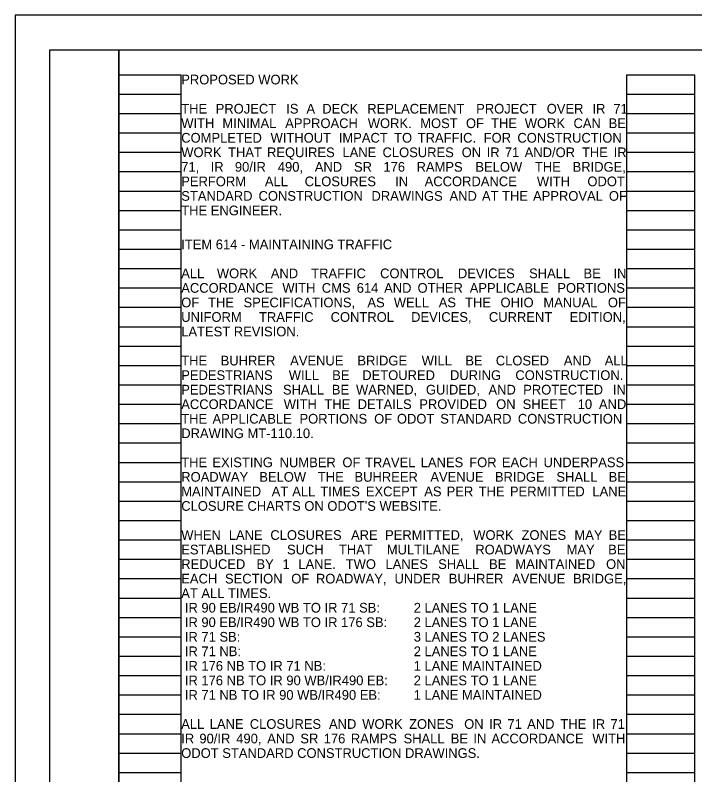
# Model space of a CAD drawing. Extents: x 0 to 43.6, y -18 to 22.
# Drawn here: x 0 to 9.82, y 11.03 to 22 of the extents above; entities that cross this region are included whole.
import ezdxf

# ---------------------------------------------------------------- set-up
doc = ezdxf.new("R2010")
doc.units = 0
for name, color, linetype in [('SH_Border', 7, 'Continuous'), ('SH_Cut_Line', 7, 'Continuous'), ('SH_Data', 7, 'Continuous'), ('SH_Text', 7, 'Continuous')]:
    doc.layers.add(name, color=color, linetype=linetype)

msp = doc.modelspace()

# ---------------------------------------------------------------- linework, layer by layer
at = {"layer": 'SH_Border'}
for points in [[(0.5, 21.5), (1.5, 21.5), (1.5, 0.5), (0.5, 0.5)], [(1.5, 21.5), (33.5, 21.5), (33.5, 0.5), (1.5, 0.5)]]:
    msp.add_lwpolyline(points, close=True, dxfattribs=at)
at = {"layer": 'SH_Cut_Line'}
msp.add_lwpolyline([(0, 0), (34, 0), (34, 22), (0, 22)], close=True, dxfattribs=at)
at = {"layer": 'SH_Data'}
for p, q in [((1.5, 0.98), (1.5, 21.14)), ((1.5, 21.14), (2.4, 21.14)), ((2.4, 0.98), (2.4, 21.14)), ((8.84, 0.98), (8.84, 21.14)), ((8.84, 21.14), (9.82, 21.14)), ((9.82, 0.98), (9.82, 21.14)), ((1.5, 20.86), (2.4, 20.86)), ((8.84, 20.86), (9.82, 20.86)), ((1.5, 20.58), (2.4, 20.58)), ((8.84, 20.58), (9.82, 20.58)), ((1.5, 20.3), (2.4, 20.3)), ((8.84, 20.3), (9.82, 20.3)), ((1.5, 20.02), (2.4, 20.02)), ((8.84, 20.02), (9.82, 20.02)), ((1.5, 19.74), (2.4, 19.74)), ((8.84, 19.74), (9.82, 19.74)), ((1.5, 19.46), (2.4, 19.46)), ((8.84, 19.46), (9.82, 19.46)), ((1.5, 19.18), (2.4, 19.18)), ((8.84, 19.18), (9.82, 19.18)), ((1.5, 18.9), (2.4, 18.9)), ((8.84, 18.9), (9.82, 18.9)), ((1.5, 18.62), (2.4, 18.62)), ((8.84, 18.62), (9.82, 18.62)), ((1.5, 18.34), (2.4, 18.34)), ((8.84, 18.34), (9.82, 18.34)), ((1.5, 18.06), (2.4, 18.06)), ((8.84, 18.06), (9.82, 18.06)), ((1.5, 17.78), (2.4, 17.78)), ((8.84, 17.78), (9.82, 17.78)), ((1.5, 17.5), (2.4, 17.5)), ((8.84, 17.5), (9.82, 17.5)), ((1.5, 17.22), (2.4, 17.22)), ((8.84, 17.22), (9.82, 17.22)), ((1.5, 16.94), (2.4, 16.94)), ((8.84, 16.94), (9.82, 16.94)), ((1.5, 16.66), (2.4, 16.66)), ((8.84, 16.66), (9.82, 16.66)), ((1.5, 16.38), (2.4, 16.38)), ((8.84, 16.38), (9.82, 16.38)), ((1.5, 16.1), (2.4, 16.1)), ((8.84, 16.1), (9.82, 16.1)), ((1.5, 15.82), (2.4, 15.82)), ((8.84, 15.82), (9.82, 15.82)), ((1.5, 15.54), (2.4, 15.54)), ((8.84, 15.54), (9.82, 15.54)), ((1.5, 15.26), (2.4, 15.26)), ((8.84, 15.26), (9.82, 15.26)), ((1.5, 14.98), (2.4, 14.98)), ((8.84, 14.98), (9.82, 14.98)), ((1.5, 14.7), (2.4, 14.7)), ((8.84, 14.7), (9.82, 14.7)), ((1.5, 14.42), (2.4, 14.42)), ((8.84, 14.42), (9.82, 14.42)), ((1.5, 14.14), (2.4, 14.14)), ((8.84, 14.14), (9.82, 14.14)), ((1.5, 13.86), (2.4, 13.86)), ((8.84, 13.86), (9.82, 13.86)), ((1.5, 13.58), (2.4, 13.58)), ((8.84, 13.58), (9.82, 13.58)), ((1.5, 13.3), (2.4, 13.3)), ((8.84, 13.3), (9.82, 13.3)), ((1.5, 13.02), (2.4, 13.02)), ((8.84, 13.02), (9.82, 13.02)), ((1.5, 12.74), (2.4, 12.74)), ((8.84, 12.74), (9.82, 12.74)), ((1.5, 12.46), (2.4, 12.46)), ((8.84, 12.46), (9.82, 12.46)), ((1.5, 12.18), (2.4, 12.18)), ((8.84, 12.18), (9.82, 12.18)), ((1.5, 11.9), (2.4, 11.9)), ((8.84, 11.9), (9.82, 11.9)), ((1.5, 11.62), (2.4, 11.62)), ((8.84, 11.62), (9.82, 11.62)), ((1.5, 11.34), (2.4, 11.34)), ((8.84, 11.34), (9.82, 11.34)), ((1.5, 11.06), (2.4, 11.06)), ((8.84, 11.06), (9.82, 11.06))]:
    msp.add_line(p, q, dxfattribs=at)

# ---------------------------------------------------------------- texts
at = {"layer": 'SH_Text'}
for s, p in [('PROPOSED WORK', (2.4, 21)), ('THE ', (2.4, 20.579)), ('PROJECT ', (2.898, 20.579)), ('IS ', (3.917, 20.579)), ('A ', (4.209, 20.579)), ('DECK ', (4.438, 20.579)), ('REPLACEMENT ', (5.088, 20.579)), ('PROJECT ', (6.662, 20.579)), ('OVER ', (7.682, 20.579)), ('IR ', (8.343, 20.579)), ('71 ', (8.645, 20.579)), ('WITH ', (2.4, 20.369)), ('MINIMAL ', (2.995, 20.369)), ('APPROACH ', (3.902, 20.369)), ('WORK. ', (5.096, 20.369)), ('MOST ', (5.854, 20.369)), ('OF ', (6.515, 20.369)), ('THE ', (6.878, 20.369)), ('WORK ', (7.365, 20.369)), ('CAN ', (8.069, 20.369)), ('BE ', (8.577, 20.369)), ('COMPLETED ', (2.4, 20.159)), ('WITHOUT ', (3.691, 20.159)), ('IMPACT ', (4.677, 20.159)), ('TO ', (5.476, 20.159)), ('TRAFFIC. ', (5.818, 20.159)), ('FOR ', (6.771, 20.159)), ('CONSTRUCTION ', (7.258, 20.159)), ('WORK ', (2.4, 19.949)), ('THAT ', (3.076, 19.949)), ('REQUIRES ', (3.64, 19.949)), ('LANE ', (4.73, 19.949)), ('CLOSURES ', (5.309, 19.949)), ('ON ', (6.453, 19.949)), ('IR ', (6.814, 19.949)), ('71 ', (7.077, 19.949)), ('AND/OR ', (7.363, 19.949)), ('THE ', (8.191, 19.949)), ('IR ', (8.65, 19.949)), ('71, ', (2.4, 19.739)), ('IR ', (2.825, 19.739)), ('90/IR ', (3.175, 19.739)), ('490, ', (3.796, 19.739)), ('AND ', (4.33, 19.739)), ('SR ', (4.896, 19.739)), ('176 ', (5.322, 19.739)), ('RAMPS ', (5.801, 19.739)), ('BELOW ', (6.651, 19.739)), ('THE ', (7.511, 19.739)), ('BRIDGE, ', (8.056, 19.739)), ('PERFORM ', (2.4, 19.529)), ('ALL ', (3.609, 19.529)), ('CLOSURES ', (4.184, 19.529)), ('IN ', (5.491, 19.529)), ('ACCORDANCE ', (5.918, 19.529)), ('WITH ', (7.54, 19.529)), ('ODOT ', (8.27, 19.529)), ('STANDARD ', (2.4, 19.319)), ('CONSTRUCTION ', (3.517, 19.319)), ('DRAWINGS ', (5.149, 19.319)), ('AND ', (6.277, 19.319)), ('AT ', (6.746, 19.319)), ('THE ', (7.037, 19.319)), ('APPROVAL ', (7.484, 19.319)), ('OF ', (8.58, 19.319)), ('THE ENGINEER.', (2.4, 19.109)), ('ITEM 614 - MAINTAINING TRAFFIC', (2.4, 18.619)), ('ALL ', (2.4, 18.2)), ('WORK ', (2.915, 18.2)), ('AND ', (3.694, 18.2)), ('TRAFFIC ', (4.278, 18.2)), ('CONTROL ', (5.274, 18.2)), ('DEVICES ', (6.398, 18.2)), ('SHALL ', (7.427, 18.2)), ('BE ', (8.214, 18.2)), ('IN ', (8.646, 18.2)), ('ACCORDANCE ', (2.4, 17.99)), ('WITH ', (3.861, 17.99)), ('CMS ', (4.431, 17.99)), ('614 ', (4.936, 17.99)), ('AND ', (5.332, 17.99)), ('OTHER ', (5.815, 17.99)), ('APPLICABLE ', (6.569, 17.99)), ('PORTIONS ', (7.835, 17.99)), ('OF ', (2.4, 17.78)), ('THE ', (2.788, 17.78)), ('SPECIFICATIONS, ', (3.3, 17.78)), ('AS ', (5.09, 17.78)), ('WELL ', (5.472, 17.78)), ('AS ', (6.121, 17.78)), ('THE ', (6.502, 17.78)), ('OHIO ', (7.014, 17.78)), ('MANUAL ', (7.634, 17.78)), ('OF ', (8.566, 17.78)), ('UNIFORM ', (2.4, 17.57)), ('TRAFFIC ', (3.523, 17.57)), ('CONTROL ', (4.559, 17.57)), ('DEVICES, ', (5.722, 17.57)), ('CURRENT ', (6.846, 17.57)), ('EDITION, ', (8.012, 17.57)), ('LATEST REVISION.  ', (2.4, 17.36)), ('THE ', (2.4, 16.94)), ('BUHRER ', (2.97, 16.94)), ('AVENUE ', (3.974, 16.94)), ('BRIDGE ', (4.946, 16.94)), ('WILL ', (5.875, 16.94)), ('BE ', (6.506, 16.94)), ('CLOSED ', (6.946, 16.94)), ('AND ', (7.929, 16.94)), ('ALL ', (8.52, 16.94)), ('PEDESTRIANS ', (2.4, 16.73)), ('WILL ', (3.954, 16.73)), ('BE ', (4.581, 16.73)), ('DETOURED ', (5.016, 16.73)), ('DURING ', (6.284, 16.73)), ('CONSTRUCTION. ', (7.229, 16.73)), ('PEDESTRIANS ', (2.4, 16.52)), ('SHALL ', (3.87, 16.52)), ('BE ', (4.576, 16.52)), ('WARNED, ', (4.926, 16.52)), ('GUIDED, ', (5.936, 16.52)), ('AND ', (6.84, 16.52)), ('PROTECTED ', (7.342, 16.52)), ('IN ', (8.638, 16.52)), ('ACCORDANCE ', (2.4, 16.31)), ('WITH ', (3.881, 16.31)), ('THE ', (4.469, 16.31)), ('DETAILS ', (4.95, 16.31)), ('PROVIDED ', (5.84, 16.31)), ('ON ', (6.951, 16.31)), ('SHEET  ', (7.334, 16.31)), ('10 ', (8.13, 16.31)), ('AND ', (8.436, 16.31)), ('APPLICABLE ', (2.852, 16.1)), ('PORTIONS ', (4.109, 16.1)), ('OF ', (5.188, 16.1)), ('ODOT ', (5.517, 16.1)), ('STANDARD ', (6.143, 16.1)), ('CONSTRUCTION ', (7.265, 16.1)), ('THE ', (2.4, 16.1)), ('DRAWING MT-110.10.', (2.4, 15.89)), ('THE ', (2.4, 15.47)), ('EXISTING ', (2.85, 15.47)), ('NUMBER ', (3.822, 15.47)), ('OF ', (4.729, 15.47)), ('TRAVEL ', (5.056, 15.47)), ('LANES ', (5.861, 15.47)), ('FOR ', (6.562, 15.47)), ('EACH ', (7.034, 15.47)), ('UNDERPASS ', (7.636, 15.47)), ('ROADWAY ', (2.4, 15.26)), ('BELOW ', (3.528, 15.26)), ('THE ', (4.374, 15.26)), ('BUHREER ', (4.904, 15.26)), ('AVENUE ', (6, 15.26)), ('BRIDGE ', (6.933, 15.26)), ('SHALL ', (7.822, 15.26)), ('BE ', (8.577, 15.26)), ('MAINTAINED  ', (2.4, 15.05)), ('AT ', (3.707, 15.05)), ('ALL ', (4.004, 15.05)), ('TIMES ', (4.41, 15.05)), ('EXCEPT ', (5.068, 15.05)), ('AS ', (5.912, 15.05)), ('PER ', (6.235, 15.05)), ('THE ', (6.698, 15.05)), ('PERMITTED ', (7.15, 15.05)), ('LANE ', (8.342, 15.05)), ("CLOSURE CHARTS ON ODOT'S WEBSITE.", (2.4, 14.84)), ('WHEN ', (2.4, 14.42)), ('LANE ', (3.087, 14.42)), ('CLOSURES ', (3.688, 14.42)), ('ARE ', (4.854, 14.42)), ('PERMITTED, ', (5.346, 14.42)), ('WORK ', (6.62, 14.42)), ('ZONES ', (7.318, 14.42)), ('MAY ', (8.082, 14.42)), ('BE ', (8.577, 14.42)), ('ESTABLISHED ', (2.4, 14.21)), ('SUCH ', (3.929, 14.21)), ('THAT ', (4.679, 14.21)), ('MULTILANE ', (5.371, 14.21)), ('ROADWAYS ', (6.65, 14.21)), ('MAY ', (7.969, 14.21)), ('BE ', (8.57, 14.21)), ('REDUCED ', (2.4, 14)), ('BY ', (3.487, 14)), ('1 ', (3.864, 14)), ('LANE. ', (4.092, 14)), ('TWO ', (4.777, 14)), ('LANES ', (5.352, 14)), ('SHALL ', (6.113, 14)), ('BE ', (6.849, 14)), ('MAINTAINED ', (7.229, 14)), ('ON ', (8.54, 14)), ('EACH ', (2.4, 13.79)), ('SECTION ', (3.032, 13.79)), ('OF ', (3.99, 13.79)), ('ROADWAY, ', (4.347, 13.79)), ('UNDER ', (5.482, 13.79)), ('BUHRER ', (6.266, 13.79)), ('AVENUE ', (7.181, 13.79)), ('BRIDGE, ', (8.063, 13.79)), ('AT ALL TIMES.', (2.4, 13.58)), (' IR 90 EB/IR490 WB TO IR 71 SB: ', (2.4, 13.37)), ('2 LANES TO 1 LANE', (5.76, 13.37)), (' IR 90 EB/IR490 WB TO IR 176 SB: ', (2.4, 13.16)), ('2 LANES TO 1 LANE', (5.76, 13.16)), (' IR 71 SB: ', (2.4, 12.95)), ('3 LANES TO 2 LANES', (5.76, 12.95)), (' IR 71 NB: ', (2.4, 12.74)), ('2 LANES TO 1 LANE', (5.76, 12.74)), (' IR 176 NB TO IR 71 NB: ', (2.4, 12.53)), ('1 LANE MAINTAINED', (5.76, 12.53)), (' IR 176 NB TO IR 90 WB/IR490 EB: ', (2.4, 12.32)), ('2 LANES TO 1 LANE', (5.76, 12.32)), (' IR 71 NB TO IR 90 WB/IR490 EB: ', (2.4, 12.11)), ('1 LANE MAINTAINED ', (5.76, 12.11)), ('ALL ', (2.4, 11.69)), ('LANE ', (2.812, 11.69)), ('CLOSURES ', (3.391, 11.69)), ('AND ', (4.535, 11.69)), ('WORK ', (5.016, 11.69)), ('ZONES  ', (5.693, 11.69)), ('ON ', (6.489, 11.69)), ('IR ', (6.85, 11.69)), ('71 ', (7.114, 11.69)), ('AND ', (7.399, 11.69)), ('THE ', (7.88, 11.69)), ('IR ', (8.339, 11.69)), ('71, ', (8.603, 11.69)), ('IR ', (2.4, 11.48)), ('90/IR ', (2.662, 11.48)), ('490, ', (3.195, 11.48)), ('AND ', (3.642, 11.48)), ('SR ', (4.121, 11.48)), ('176 ', (4.459, 11.48)), ('RAMPS ', (4.851, 11.48)), ('SHALL ', (5.613, 11.48)), ('BE ', (6.295, 11.48)), ('IN ', (6.622, 11.48)), ('ACCORDANCE ', (6.883, 11.48)), ('WITH ', (8.341, 11.48)), ('ODOT STANDARD CONSTRUCTION DRAWINGS.', (2.4, 11.27))]:
    msp.add_text(s, height=0.14, dxfattribs=at).set_placement(p)

doc.saveas('drawing.dxf')
